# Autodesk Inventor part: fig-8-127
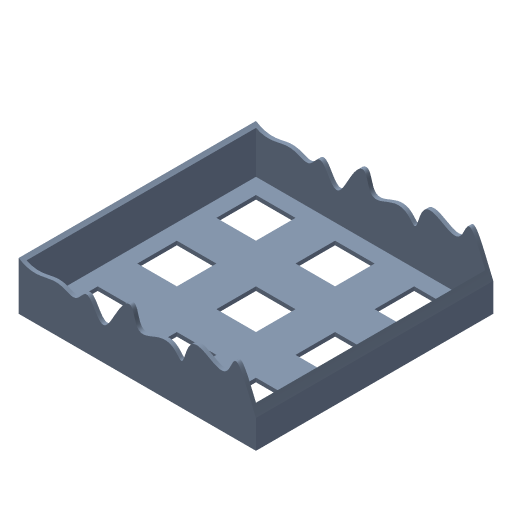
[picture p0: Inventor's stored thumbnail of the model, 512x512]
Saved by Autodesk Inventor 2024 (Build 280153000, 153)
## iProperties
Shininess: 64.0
Length Units: 11269
Angle Units: 11279
Time Units: 11290
Mass Units: 11283
Length Display Precision: 3
Angle Display Precision: 2
Compacted: True
Part Number: fig-8-127
Document SubType Name: Modeling
Created: 2002-12
Designer: deepak
Density: 1 g/cm^3
Material: Generic
Appearance: Light Steel Blue
Density: 0.0
Volumn: 0.0
Area: 0.0
PropertySet Name: Model Information
Control State: 0
Master: False
Checked Out: False
Author: deepak
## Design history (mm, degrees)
sketch "Sketch1"
  geometry: L1 (-32.188, 30.089)-(27.812, 30.089); L2 (27.812, 30.089)-(27.812, -29.911); L3 (27.812, -29.911)-(-32.188, -29.911); L4 (-32.188, -29.911)-(-32.188, 30.089)
  constraints: 8 end point, 2 parallel, 1 horizontal, 1 perpendicular
  dimensions: "d0" = 60 distance of L1.start L1.end; "d1" = 60 distance of L3.end L1.start
extrude "Extrusion1" new body sketch "Sketch1" stored distance "d2" = 20; taper "d3" = 0 deg
shell "Shell2" dims "d21" = 1
sketch "Sketch5"
  geometry: L1 (-27.812, 30.089)-(32.188, 30.089) reference; L2 (-27.812, -29.911)-(-27.812, 30.089) reference; L3 (-22.812, 25.089)-(-12.812, 25.089); L4 (-12.812, 25.089)-(-12.812, 15.089); L5 (-12.812, 15.089)-(-22.812, 15.089); L6 (-22.812, 15.089)-(-22.812, 25.089)
  constraints: 8 end point, 2 parallel, 1 horizontal, 1 perpendicular
  dimensions: "d8" = 10 distance of L3.start L3.end; "d9" = 10 distance of L5.end L3.start; "d10" = 5 distance between parallel lines of L2 L6; "d11" = 5 distance between parallel lines of L1 L3
extrude "Extrusion2" cut sketch "Sketch5" distance "d12" = 50; taper "d13" = 0 deg
pattern_linear "Rectangular Pattern1" dims "d16" = 20, "d19" = 20
sketch "Sketch2"
  geometry: 17 further points
  constraints: 17 other
extrude_surface "ExtrusionSrf1" sketch "Sketch2" dims "d4" = 70, "d5" = 0
split "Split2"
body "Solid1"
body "Srf1"
